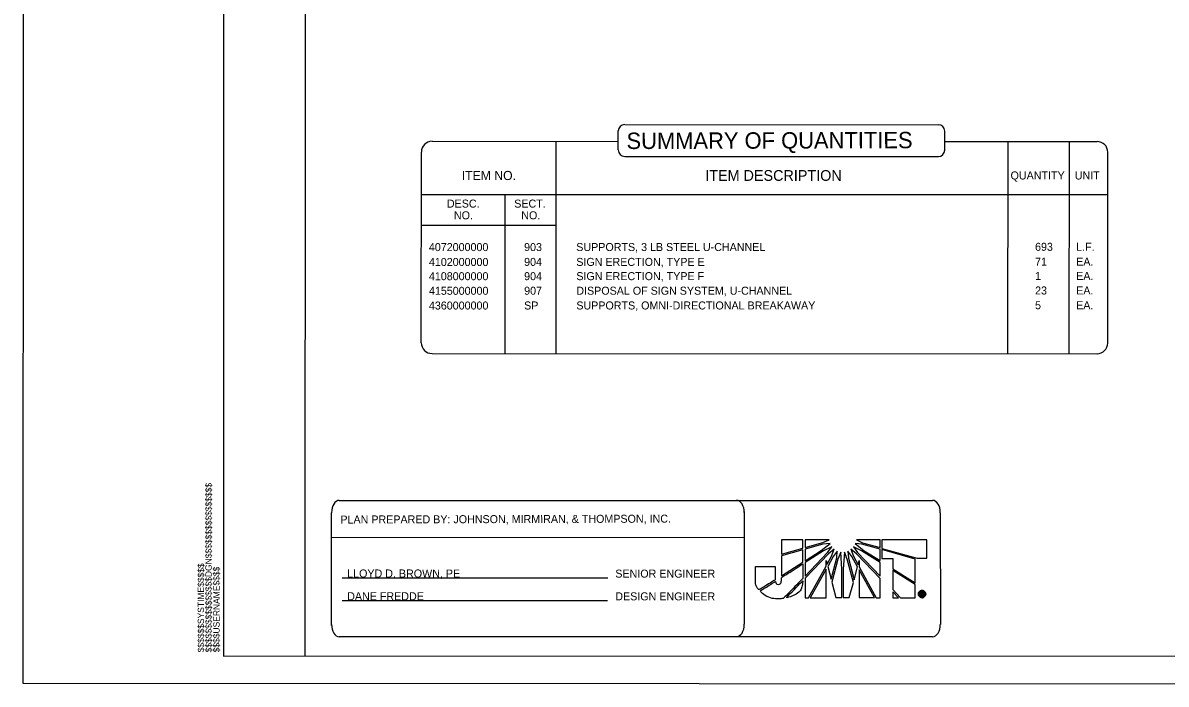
# Model space of a CAD drawing. Extents: x 50703 to 52785, y 49383 to 50479.
# Drawn here: x 50703 to 51651, y 49383 to 49931 of the extents above; entities that cross this region are included whole.
import ezdxf

# ---------------------------------------------------------------- set-up
doc = ezdxf.new("R2010")
doc.units = 0
for name, color, linetype in [('Default', 7, 'Continuous'), ('Old_Level_18', 7, 'Continuous'), ('Old_Level_41', 7, 'Continuous'), ('Old_Level_50', 7, 'Continuous'), ('Sheet Plot Border Outside CELL', 7, 'Continuous'), ('Sheet Title CELL', 7, 'Continuous')]:
    doc.layers.add(name, color=color, linetype=linetype)

msp = doc.modelspace()

# ---------------------------------------------------------------- linework, layer by layer
at = {"layer": 'Default'}
for p, q in [((51144.9, 49656.67), (51144.92, 49832.65)), ((51519.84, 49656.61), (51519.88, 49832.59)), ((51570.69, 49656.3), (51570.94, 49832.53)), ((51033.19, 49788.64), (51519.87, 49788.65)), ((51102.64, 49656.73), (51102.64, 49788.64)), ((51519.87, 49788.65), (51570.88, 49788.65)), ((51570.88, 49788.65), (51602.66, 49788.65)), ((51103.12, 49764.18), (51103.12, 49764.18)), ((51033.18, 49763.06), (51144.91, 49763.06)), ((50965.09, 49534.88), (51457.31, 49534.93)), ((50958.71, 49431.24), (50958.68, 49524.68)), ((51301.08, 49525.65), (51301.1, 49432.21)), ((51463.72, 49524.69), (51463.73, 49432.13)), ((50958.67, 49504.26), (51301.11, 49504.41)), ((51349.65, 49502.12), (51331.88, 49502.12)), ((51331.88, 49502.12), (51331.88, 49490.33)), ((51349.65, 49495.26), (51349.65, 49502.12)), ((51371.5, 49502.21), (51351.5, 49502.21)), ((51351.5, 49502.21), (51351.5, 49495.85)), ((51351.5, 49495.85), (51366.39, 49499.96)), ((51366.39, 49498.58), (51351.5, 49494.47)), ((51364.84, 49493.3), (51372.2, 49499.28)), ((51366.39, 49499.96), (51371.5, 49502.21)), ((51372.2, 49499.28), (51366.39, 49498.58)), ((51393.14, 49499.28), (51400.59, 49493.19)), ((51398.62, 49498.58), (51393.14, 49499.28)), ((51413.84, 49502.13), (51394.13, 49502.22)), ((51394.13, 49502.22), (51399.12, 49499.87)), ((51413.84, 49494.39), (51398.62, 49498.58)), ((51399.12, 49499.87), (51413.84, 49495.74)), ((51413.84, 49495.74), (51413.84, 49502.13)), ((51452.57, 49502.22), (51415.22, 49502.22)), ((51415.22, 49502.22), (51415.22, 49495.36)), ((51452.58, 49486.92), (51452.57, 49502.22)), ((51331.88, 49490.33), (51349.65, 49495.26)), ((51349.65, 49493.97), (51331.88, 49488.99)), ((51331.88, 49488.99), (51331.88, 49472.42)), ((51349.65, 49483.68), (51349.65, 49493.97)), ((51351.5, 49494.47), (51351.5, 49484.85)), ((51351.5, 49484.85), (51364.84, 49493.3)), ((51366.89, 49493.1), (51351.5, 49483.3)), ((51351.5, 49472.22), (51370.24, 49491.72)), ((51371, 49490.75), (51351.5, 49470.34)), ((51373.67, 49496.53), (51366.89, 49493.1)), ((51369.83, 49481.92), (51373.55, 49488.7)), ((51370.24, 49491.72), (51373.67, 49496.53)), ((51375.72, 49494.39), (51371, 49490.75)), ((51373.55, 49488.7), (51375.72, 49494.39)), ((51378.27, 49492.8), (51374.75, 49488.29)), ((51377.77, 49487.32), (51378.27, 49492.8)), ((51381.2, 49492.01), (51378.77, 49486.32)), ((51381.97, 49478), (51381.2, 49492.01)), ((51384.14, 49492.01), (51383.23, 49478)), ((51386.48, 49486.32), (51384.14, 49492.01)), ((51386.98, 49492.8), (51387.57, 49487.12)), ((51390.41, 49488.29), (51386.98, 49492.8)), ((51389.5, 49494.39), (51391.67, 49488.7)), ((51394.22, 49490.75), (51389.5, 49494.39)), ((51391.58, 49496.53), (51395.01, 49491.63)), ((51398.45, 49493.1), (51391.58, 49496.53)), ((51391.67, 49488.7), (51395.49, 49481.63)), ((51413.72, 49470.17), (51394.22, 49490.75)), ((51395.01, 49491.63), (51413.72, 49472.02)), ((51413.72, 49483.39), (51398.45, 49493.1)), ((51400.59, 49493.19), (51413.72, 49484.98)), ((51413.72, 49484.98), (51413.84, 49494.39)), ((51415.22, 49495.36), (51415.22, 49495.15)), ((51415.22, 49495.15), (51444.63, 49486.92)), ((51415.22, 49494.1), (51415.22, 49493.98)), ((51442.75, 49486.24), (51415.22, 49494.1)), ((51415.22, 49493.98), (51415.22, 49486.83)), ((51331.88, 49472.42), (51349.65, 49483.68)), ((51351.5, 49483.3), (51351.5, 49472.22)), ((51354.44, 49454.21), (51368.95, 49480.46)), ((51368.95, 49480.46), (51368.95, 49485.15)), ((51368.95, 49485.15), (51369.83, 49481.92)), ((51374.75, 49488.29), (51370.33, 49480.25)), ((51370.33, 49480.25), (51373.17, 49469.58)), ((51373.17, 49469.58), (51377.77, 49487.32)), ((51378.77, 49486.32), (51373.76, 49467.12)), ((51391.59, 49466.82), (51386.48, 49486.32)), ((51387.57, 49487.12), (51392.17, 49469.17)), ((51395.02, 49479.96), (51390.41, 49488.29)), ((51392.17, 49469.17), (51395.02, 49479.96)), ((51395.49, 49481.63), (51396.39, 49485.15)), ((51396.39, 49485.15), (51396.39, 49479.96)), ((51396.39, 49479.96), (51410.59, 49454.22)), ((51413.72, 49472.02), (51413.72, 49483.39)), ((51415.22, 49486.83), (51424.34, 49486.83)), ((51424.34, 49486.83), (51424.34, 49478.29)), ((51442.75, 49466.63), (51442.75, 49486.24)), ((51444.63, 49486.92), (51452.58, 49486.92)), ((50967.45, 49470.81), (51187.76, 49470.71)), ((51351.5, 49470.34), (51351.5, 49454.21)), ((51368.95, 49477.91), (51355.81, 49454.21)), ((51369.07, 49454.21), (51368.95, 49477.91)), ((51381.97, 49454.3), (51381.97, 49478)), ((51383.23, 49478), (51383.23, 49454.3)), ((51409.12, 49454.31), (51396.39, 49477.41)), ((51396.39, 49477.41), (51396.4, 49454.3)), ((51413.73, 49454.22), (51413.72, 49470.17)), ((51424.34, 49478.29), (51442.75, 49466.63)), ((51424.34, 49476.83), (51424.34, 49460.93)), ((51442.76, 49465.25), (51424.34, 49476.83)), ((51373.76, 49467.12), (51377.1, 49454.3)), ((51388.16, 49454.3), (51391.59, 49466.82)), ((51424.34, 49460.93), (51430.71, 49454.22)), ((51442.76, 49454.22), (51442.76, 49465.25)), ((51448.55, 49460.22), (51448.55, 49459.65)), ((51448.55, 49459.65), (51448.55, 49460.22)), ((50967.44, 49451.94), (51187.75, 49451.82)), ((51351.5, 49454.21), (51354.44, 49454.21)), ((51355.81, 49454.21), (51369.07, 49454.21)), ((51377.1, 49454.3), (51381.97, 49454.3)), ((51383.23, 49454.3), (51388.16, 49454.3)), ((51396.4, 49454.3), (51409.12, 49454.31)), ((51410.59, 49454.22), (51413.73, 49454.22)), ((51428.95, 49454.22), (51424.34, 49459.2)), ((51424.34, 49459.2), (51424.34, 49454.22)), ((51424.34, 49454.22), (51428.95, 49454.22)), ((51430.71, 49454.22), (51442.76, 49454.22)), ((51447.44, 49455.9), (51447.44, 49458.62)), ((51447.44, 49458.62), (51448.55, 49458.62)), ((51448.05, 49455.9), (51447.44, 49455.9)), ((51448.55, 49458.1), (51448.05, 49458.1)), ((51448.05, 49458.1), (51448.05, 49457.46)), ((51448.05, 49457.46), (51448.55, 49457.46)), ((51448.55, 49456.96), (51448.05, 49456.96)), ((51448.05, 49456.96), (51448.05, 49455.9)), ((51448.55, 49458.62), (51448.55, 49458.1)), ((51448.55, 49458.1), (51448.55, 49458.62)), ((51448.55, 49458.62), (51448.72, 49458.62)), ((51448.62, 49458.1), (51448.55, 49458.1)), ((51448.55, 49457.46), (51448.55, 49456.96)), ((51448.55, 49456.96), (51448.55, 49457.46)), ((51448.55, 49457.46), (51448.57, 49457.46)), ((51448.57, 49456.96), (51448.55, 49456.96)), ((51448.55, 49454.84), (51448.55, 49454.25)), ((51448.55, 49454.25), (51448.55, 49454.84)), ((51448.55, 49454.84), (51448.57, 49454.84)), ((51448.57, 49454.25), (51448.55, 49454.25)), ((51457.31, 49421.89), (50965.1, 49421.83))]:
    msp.add_line(p, q, dxfattribs=at)
for points in [[(51331.88, 49490.33), (51349.65, 49495.26), (51349.65, 49502.12), (51331.88, 49502.12), (51331.88, 49490.33)], [(51366.39, 49499.96), (51371.5, 49502.21), (51351.5, 49502.21), (51351.5, 49495.85), (51366.39, 49499.96)], [(51351.5, 49494.47), (51351.5, 49484.85), (51364.84, 49493.3), (51372.2, 49499.28), (51366.39, 49498.58), (51351.5, 49494.47)], [(51393.14, 49499.28), (51400.59, 49493.19), (51413.72, 49484.98), (51413.84, 49494.39), (51398.62, 49498.58), (51393.14, 49499.28)], [(51399.12, 49499.87), (51413.84, 49495.74), (51413.84, 49502.13), (51394.13, 49502.22), (51399.12, 49499.87)], [(51452.57, 49502.22), (51415.22, 49502.22), (51415.22, 49495.36), (51415.22, 49495.15), (51444.63, 49486.92), (51452.58, 49486.92), (51452.57, 49502.22)], [(51331.88, 49472.42), (51349.65, 49483.68), (51349.65, 49493.97), (51331.88, 49488.99), (51331.88, 49472.42)], [(51351.5, 49483.3), (51351.5, 49472.22), (51370.24, 49491.72), (51373.67, 49496.53), (51366.89, 49493.1), (51351.5, 49483.3)], [(51375.72, 49494.39), (51371, 49490.75), (51351.5, 49470.34), (51351.5, 49454.21), (51354.44, 49454.21), (51368.95, 49480.46), (51368.95, 49485.15), (51369.83, 49481.92), (51373.55, 49488.7), (51375.72, 49494.39)], [(51378.27, 49492.8), (51374.75, 49488.29), (51370.33, 49480.25), (51373.17, 49469.58), (51377.77, 49487.32), (51378.27, 49492.8)], [(51378.77, 49486.32), (51373.76, 49467.12), (51377.1, 49454.3), (51381.97, 49454.3), (51381.97, 49478), (51381.2, 49492.01), (51378.77, 49486.32)], [(51384.14, 49492.01), (51383.23, 49478), (51383.23, 49454.3), (51388.16, 49454.3), (51391.59, 49466.82), (51386.48, 49486.32), (51384.14, 49492.01)], [(51386.98, 49492.8), (51387.57, 49487.12), (51392.17, 49469.17), (51395.02, 49479.96), (51390.41, 49488.29), (51386.98, 49492.8)], [(51389.5, 49494.39), (51391.67, 49488.7), (51395.49, 49481.63), (51396.39, 49485.15), (51396.39, 49479.96), (51410.59, 49454.22), (51413.73, 49454.22), (51413.72, 49470.17), (51394.22, 49490.75), (51389.5, 49494.39)], [(51391.58, 49496.53), (51395.01, 49491.63), (51413.72, 49472.02), (51413.72, 49483.39), (51398.45, 49493.1), (51391.58, 49496.53)], [(51415.22, 49494.1), (51415.22, 49493.98), (51415.22, 49486.83), (51424.34, 49486.83), (51424.34, 49478.29), (51442.75, 49466.63), (51442.75, 49486.24), (51415.22, 49494.1)], [(51355.81, 49454.21), (51369.07, 49454.21), (51368.95, 49477.91), (51355.81, 49454.21)], [(51396.4, 49454.3), (51409.12, 49454.31), (51396.39, 49477.41), (51396.4, 49454.3)], [(51424.34, 49476.83), (51424.34, 49460.93), (51430.71, 49454.22), (51442.76, 49454.22), (51442.76, 49465.25), (51424.34, 49476.83), (51424.34, 49476.83)], [(51424.34, 49454.22), (51424.34, 49454.22), (51428.95, 49454.22), (51424.34, 49459.2), (51424.34, 49454.22)], [(51448.55, 49458.62), (51447.44, 49458.62), (51447.44, 49455.9), (51448.05, 49455.9), (51448.05, 49456.96), (51448.55, 49456.96), (51448.55, 49457.46), (51448.05, 49457.46), (51448.05, 49458.1), (51448.55, 49458.1), (51448.55, 49458.62)], [(51449.73, 49456.54), (51449.73, 49456.39), (51449.76, 49456.29), (51449.76, 49456.2), (51449.83, 49455.9), (51449.26, 49455.9)]]:
    msp.add_lwpolyline(points, dxfattribs=at)
for centre, major_axis, start_param, end_param in [((50965.1, 49524.69), (0, 10.24), 0.000702, 1.571498), ((51294.69, 49524.77), (0, 10.24), 4.713091, 6.283887), ((51457.31, 49524.69), (0, 10.24), 4.713091, 6.283887), ((50965.1, 49432.12), (0, -10.24), 4.713091, 6.283887), ((51294.69, 49432.2), (0, -10.24), 0.000702, 1.571498), ((51457.31, 49432.13), (0, -10.24), 0.000702, 1.571498)]:
    msp.add_ellipse(centre, major_axis=major_axis, ratio=0.62659, start_param=start_param, end_param=end_param, dxfattribs=at)
for points, degree in [([(51326.78, 49480.04), (51326.78, 49480.04), (51310.33, 49480.04), (51310.33, 49480.04), (51310.33, 49480.04), (51310.33, 49469.75), (51310.33, 49469.75), (51310.33, 49469.75), (51310.33, 49468.66), (51310.33, 49468.66), (51310.33, 49465.44), (51311.39, 49462.89), (51313.27, 49460.75), (51313.27, 49460.75), (51326.78, 49468.96), (51326.78, 49469.16), (51326.78, 49469.16), (51326.78, 49480.04), (51326.78, 49480.04)], 3), ([(51326.78, 49480.04), (51326.78, 49480.04), (51310.33, 49480.04), (51310.33, 49480.04), (51310.33, 49480.04), (51310.33, 49469.75), (51310.33, 49469.75), (51310.33, 49469.75), (51310.33, 49468.66), (51310.33, 49468.66), (51310.33, 49465.44), (51311.39, 49462.89), (51313.27, 49460.75), (51313.27, 49460.75), (51326.78, 49468.96), (51326.78, 49469.16), (51326.78, 49469.16), (51326.78, 49480.04), (51326.78, 49480.04)], 3), ([(51329.33, 49465.23), (51328.28, 49465.23), (51327.37, 49465.82), (51326.99, 49467.78), (51326.99, 49467.78), (51314.23, 49459.9), (51314.23, 49459.9), (51318.16, 49455.76), (51324.44, 49453.3), (51329.75, 49453.3), (51331.12, 49453.3), (51332.18, 49453.42), (51333.65, 49453.71), (51333.65, 49453.71), (51349.65, 49470.25), (51349.65, 49470.25), (51349.65, 49470.25), (51349.65, 49482.21), (51349.65, 49482.21), (51349.65, 49482.21), (51331.88, 49470.92), (51331.88, 49470.92), (51331.89, 49466.44), (51330.8, 49465.23), (51329.33, 49465.23)], 3), ([(51329.33, 49465.23), (51328.28, 49465.23), (51327.37, 49465.82), (51326.99, 49467.78), (51326.99, 49467.78), (51314.23, 49459.9), (51314.23, 49459.9), (51318.16, 49455.76), (51324.44, 49453.3), (51329.75, 49453.3), (51331.12, 49453.3), (51332.18, 49453.42), (51333.65, 49453.71), (51333.65, 49453.71), (51349.65, 49470.25), (51349.65, 49470.25), (51349.65, 49470.25), (51349.65, 49482.21), (51349.65, 49482.21), (51349.65, 49482.21), (51331.88, 49470.92), (51331.88, 49470.92), (51331.89, 49466.44), (51330.8, 49465.23), (51329.33, 49465.23)], 3), ([(51349.65, 49468.37), (51349.65, 49468.37), (51335.82, 49454.09), (51335.82, 49454.09), (51342.59, 49455.76), (51349.33, 49460.25), (51349.65, 49468.37)], 3), ([(51349.65, 49468.37), (51349.65, 49468.37), (51335.82, 49454.09), (51335.82, 49454.09), (51342.59, 49455.76), (51349.33, 49460.25), (51349.65, 49468.37)], 3), ([(51448.55, 49454.25), (51447.73, 49454.25), (51447.02, 49454.54), (51446.42, 49455.13), (51445.83, 49455.7), (51445.53, 49456.42), (51445.53, 49457.26), (51445.53, 49458.1), (51445.83, 49458.81), (51446.42, 49459.36), (51447.02, 49459.93), (51447.71, 49460.22), (51448.55, 49460.22), (51448.55, 49460.22), (51448.55, 49459.65), (51448.55, 49459.65), (51447.88, 49459.65), (51447.31, 49459.43), (51446.84, 49458.99), (51446.37, 49458.52), (51446.13, 49457.92), (51446.13, 49457.26), (51446.13, 49456.59), (51446.37, 49456), (51446.84, 49455.53), (51447.31, 49455.06), (51447.88, 49454.84), (51448.55, 49454.84), (51448.55, 49454.84), (51448.55, 49454.25), (51448.55, 49454.25), (51448.55, 49454.25), (51448.55, 49454.25), (51448.55, 49454.25)], 3), ([(51448.55, 49454.25), (51447.73, 49454.25), (51447.02, 49454.54), (51446.42, 49455.13), (51445.83, 49455.7), (51445.53, 49456.42), (51445.53, 49457.26), (51445.53, 49458.1), (51445.83, 49458.81), (51446.42, 49459.36), (51447.02, 49459.93), (51447.71, 49460.22), (51448.55, 49460.22)], 3), ([(51451.58, 49457.26), (51451.58, 49456.42), (51451.29, 49455.7), (51450.72, 49455.11), (51450.13, 49454.54), (51449.41, 49454.25), (51448.57, 49454.25), (51448.57, 49454.25), (51448.57, 49454.25), (51448.55, 49454.25), (51448.55, 49454.25), (51448.55, 49454.84), (51448.55, 49454.84), (51448.57, 49454.84), (51448.57, 49454.84), (51448.57, 49454.84), (51449.24, 49454.84), (51449.81, 49455.06), (51450.28, 49455.53), (51450.74, 49456), (51450.99, 49456.59), (51450.99, 49457.26), (51450.99, 49457.93), (51450.74, 49458.52), (51450.28, 49458.99), (51449.81, 49459.43), (51449.24, 49459.65), (51448.55, 49459.65), (51448.55, 49459.65), (51448.55, 49460.22), (51448.55, 49460.22), (51449.39, 49460.22), (51450.1, 49459.93), (51450.69, 49459.36), (51451.29, 49458.81), (51451.58, 49458.1), (51451.58, 49457.26), (51451.58, 49457.26), (51451.58, 49457.26), (51451.58, 49457.26)], 3), ([(51448.55, 49460.22), (51449.39, 49460.22), (51450.1, 49459.93), (51450.69, 49459.36), (51451.29, 49458.81), (51451.58, 49458.1), (51451.58, 49457.26)], 3), ([(51448.55, 49459.65), (51447.88, 49459.65), (51447.31, 49459.43), (51446.84, 49458.99), (51446.37, 49458.52), (51446.13, 49457.92), (51446.13, 49457.26), (51446.13, 49456.59), (51446.37, 49456), (51446.84, 49455.53), (51447.31, 49455.06), (51447.88, 49454.84), (51448.55, 49454.84)], 3), ([(51448.57, 49454.84), (51449.24, 49454.84), (51449.81, 49455.06), (51450.28, 49455.53), (51450.74, 49456), (51450.99, 49456.59), (51450.99, 49457.26), (51450.99, 49457.93), (51450.74, 49458.52), (51450.28, 49458.99), (51449.81, 49459.43), (51449.24, 49459.65), (51448.55, 49459.65)], 3), ([(51448.55, 49456.96), (51448.55, 49456.96), (51448.55, 49457.46), (51448.55, 49457.46), (51448.55, 49457.46), (51448.57, 49457.46), (51448.57, 49457.46), (51448.97, 49457.46), (51449.16, 49457.58), (51449.16, 49457.8), (51449.16, 49458), (51448.99, 49458.1), (51448.62, 49458.1), (51448.62, 49458.1), (51448.55, 49458.1), (51448.55, 49458.1), (51448.55, 49458.1), (51448.55, 49458.62), (51448.55, 49458.62), (51448.55, 49458.62), (51448.72, 49458.62), (51448.72, 49458.62), (51449.41, 49458.62), (51449.76, 49458.34), (51449.76, 49457.8), (51449.76, 49457.55), (51449.66, 49457.36), (51449.44, 49457.21), (51449.61, 49457.11), (51449.71, 49456.89), (51449.73, 49456.54), (51449.73, 49456.54), (51449.73, 49456.39), (51449.73, 49456.39), (51449.73, 49456.39), (51449.76, 49456.29), (51449.76, 49456.29), (51449.76, 49456.29), (51449.76, 49456.2), (51449.76, 49456.2), (51449.76, 49456.2), (51449.83, 49455.9), (51449.83, 49455.9), (51449.83, 49455.9), (51449.26, 49455.9), (51449.26, 49455.9), (51449.19, 49456.05), (51449.14, 49456.2), (51449.14, 49456.39), (51449.14, 49456.64), (51449.11, 49456.79), (51449.04, 49456.86), (51448.97, 49456.91), (51448.82, 49456.96), (51448.57, 49456.96), (51448.57, 49456.96), (51448.55, 49456.96), (51448.55, 49456.96)], 3), ([(51448.57, 49457.46), (51448.97, 49457.46), (51449.16, 49457.58), (51449.16, 49457.8), (51449.16, 49458), (51448.99, 49458.1), (51448.62, 49458.1)], 3), ([(51451.58, 49457.26), (51451.58, 49456.42), (51451.29, 49455.7), (51450.72, 49455.11), (51450.13, 49454.54), (51449.41, 49454.25), (51448.57, 49454.25)], 3), ([(51449.04, 49456.86), (51448.97, 49456.91), (51448.82, 49456.96), (51448.57, 49456.96)], 2), ([(51448.72, 49458.62), (51449.41, 49458.62), (51449.76, 49458.34), (51449.76, 49457.8), (51449.76, 49457.55), (51449.66, 49457.36), (51449.44, 49457.21)], 3), ([(51449.26, 49455.9), (51449.19, 49456.05), (51449.14, 49456.2), (51449.14, 49456.39), (51449.14, 49456.64), (51449.11, 49456.79), (51449.04, 49456.86)], 3), ([(51449.44, 49457.21), (51449.61, 49457.11), (51449.71, 49456.89), (51449.73, 49456.54)], 2)]:
    msp.add_open_spline(points, degree=degree, dxfattribs=at)
at = {"layer": 'Old_Level_18'}
msp.add_lwpolyline([(52369.04, 50455.98), (50869.05, 50455.87), (50869.12, 49405.87), (52369.12, 49405.98)], close=True, dxfattribs=at)
at = {"layer": 'Old_Level_50'}
msp.add_line((50702.62, 49383.36), (50702.62, 49383.36), dxfattribs=at)
at = {"layer": 'Sheet Plot Border Outside CELL'}
msp.add_lwpolyline([(52386.04, 50478.48), (50703.13, 50479.27), (50702.62, 49383.36), (52385.53, 49382.58)], close=True, dxfattribs=at)
at = {"layer": 'Sheet Title CELL'}
for p, q in [((51196.58, 49825.6), (51196.59, 49841.31)), ((51467.44, 49825.45), (51467.45, 49841.16)), ((51042.12, 49832.7), (51196.59, 49832.62)), ((51467.44, 49832.66), (51593.77, 49832.5)), ((51033.14, 49665.67), (51033.21, 49823.79)), ((51602.61, 49665.47), (51602.68, 49823.58)), ((51042.04, 49656.75), (51593.69, 49656.55))]:
    msp.add_line(p, q, dxfattribs=at)
for points in [[(50936.87, 49405.88), (50937.36, 50455.88)], [(51201.94, 49846.65), (51462.1, 49846.5)], [(51201.93, 49820.25), (51462.09, 49820.1)]]:
    msp.add_lwpolyline(points, dxfattribs=at)
for centre, radius, start, end in [((51201.94, 49841.3), 5.35, 89.97482, 179.97482), ((51462.1, 49841.16), 5.35, 359.97482, 89.97482), ((51042.12, 49823.79), 8.91, 89.97482, 179.97482), ((51593.77, 49823.59), 8.91, 359.97482, 89.97482), ((51201.93, 49825.59), 5.35, 179.97482, 269.97482), ((51462.09, 49825.45), 5.35, 269.97482, 359.97482), ((51042.05, 49665.66), 8.91, 179.97482, 269.97482), ((51593.7, 49665.46), 8.91, 269.97482, 359.97482)]:
    msp.add_arc(centre, radius, start, end, dxfattribs=at)

# ---------------------------------------------------------------- texts
at = {"layer": 'Default'}
for s, height, rotation, p in [('SUMMARY OF QUANTITIES', 13.5942, 0.15707, (51203.39, 49826.3)), ('ITEM NO.', 7.574, 0.00141, (51066.71, 49800.58)), ('ITEM DESCRIPTION', 8.91, 0.00141, (51268.72, 49799.92)), ('QUANTITY', 6.638, 0.00141, (51522.01, 49801.06)), ('UNIT', 6.638, 0.00141, (51575.25, 49801.06)), ('DESC.', 6.638, 0.00141, (51054.38, 49777.74)), ('SECT.', 6.638, 0.00141, (51110.24, 49777.74)), ('NO.', 6.638, 0.00141, (51060.24, 49768.03)), ('NO.', 6.638, 0.00141, (51116.1, 49768.04)), ('693', 6.638, 0.00141, (51542.29, 49741.92)), ('71', 6.638, 0.00141, (51542.32, 49729.58)), ('1', 6.64, 0.00141, (51542.33, 49717.77)), ('23', 6.638, 0.00141, (51542.33, 49705.69)), ('EA.', 6.638, 0.00141, (51576.43, 49705.69)), ('5', 6.64, 0.00141, (51542.32, 49693.46)), ('EA.', 6.638, 0.00141, (51576.42, 49693.46)), ('PLAN PREPARED BY: JOHNSON, MIRMIRAN, & THOMPSON, INC.', 6.6381, 0.15565, (50966.06, 49515.74)), ('LLOYD D. BROWN, PE', 6.6381, 359.97341, (50971.67, 49471.02)), ('SENIOR ENGINEER', 6.6381, 359.97341, (51194.1, 49470.91)), ('DANE FREDDE', 6.6381, 359.97341, (50971.66, 49452.15)), ('DESIGN ENGINEER', 6.6381, 359.97341, (51194.09, 49452.05))]:
    msp.add_text(s, height=height, rotation=rotation, dxfattribs=at).set_placement(p)
for s, height, p in [('4072000000', 6.638, (51039.44, 49741.67)), ('903', 6.638, (51118.44, 49741.7)), ('SUPPORTS, 3 LB STEEL U-CHANNEL', 6.6381, (51161.71, 49741.72)), ('L.F.', 6.638, (51576.39, 49741.92)), ('4102000000', 6.638, (51039.46, 49729.33)), ('904', 6.638, (51118.45, 49729.37)), ('SIGN ERECTION, TYPE E', 6.6381, (51161.73, 49729.39)), ('EA.', 6.638, (51576.42, 49729.58)), ('4108000000', 6.638, (51039.46, 49717.52)), ('904', 6.638, (51118.46, 49717.56)), ('SIGN ERECTION, TYPE F', 6.6381, (51161.74, 49717.58)), ('EA.', 6.638, (51576.43, 49717.77)), ('4155000000', 6.638, (51039.48, 49705.44)), ('907', 6.638, (51118.47, 49705.48)), ('DISPOSAL OF SIGN SYSTEM, U-CHANNEL', 6.6381, (51161.75, 49705.5)), ('4360000000', 6.638, (51039.47, 49693.21)), ('SP', 6.638, (51118.47, 49693.25)), ('SUPPORTS, OMNI-DIRECTIONAL BREAKAWAY', 6.6381, (51161.75, 49693.27))]:
    msp.add_text(s, height=height, dxfattribs=at).set_placement(p)
at = {"layer": 'Old_Level_41'}
for s, p in [('$$$$$$$$$$$$$$$$DGN$$$$$$$$$$$$$$$$', (50859.27, 49408.87)), ('$$$$$$SYSTIME$$$$$', (50852.92, 49408.97)), ('$$$$USERNAME$$$$', (50865.82, 49408.92))]:
    msp.add_text(s, height=5.25, rotation=90.00421, dxfattribs=at).set_placement(p)

doc.saveas('drawing.dxf')
